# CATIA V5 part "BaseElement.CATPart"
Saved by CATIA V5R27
Part number: 基准元素
Bounding box of the stored display mesh (mm): x 0 to 0, y 0 to 0, z 0 to 20
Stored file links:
  E:\资料\Catia超级副本\GB 70.1螺钉_带平垫\Part1.CATPart
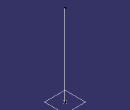
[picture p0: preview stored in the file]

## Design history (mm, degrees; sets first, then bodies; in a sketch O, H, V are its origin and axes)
AxisSystem1: origin (0, 0, 0), X (1, 0, 0), Y (0, 1, 0), Z (0, 0, 1)
Set1
  Point1: (0, 0, 0), in AxisSystem1
  Line1: type PtDir, RefPoint Point1, Direction (0, 0, 1), Start 0, End 20
  Plane1: type Normal, Curve Line1, RefPoint Point1, Ratio 0
Body1 (main body)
